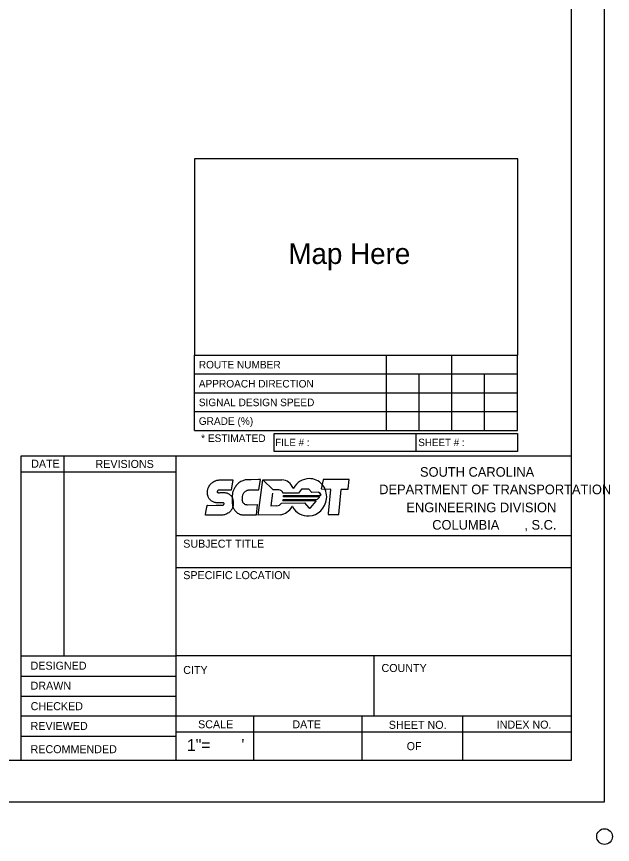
# Model space of a CAD drawing. Extents: x 0 to 3.01, y -0.05 to 1.83.
# Drawn here: x 2.332 to 3.009, y -0.048 to 0.892 of the extents above; entities that cross this region are included whole.
import ezdxf

# ---------------------------------------------------------------- set-up
doc = ezdxf.new("R2010")
doc.units = 0
doc.layers.add('RD_SHT_IplotShp', color=7, linetype='Continuous')
doc.layers.add('TR_TS_Border', color=7, linetype='Continuous')

msp = doc.modelspace()

# ---------------------------------------------------------------- linework, layer by layer
at = {"layer": 'RD_SHT_IplotShp'}
msp.add_lwpolyline([(0, 0), (3, 0), (3, 1.83333), (0, 1.83333)], close=True, dxfattribs=at)
at = {"layer": 'TR_TS_Border'}
for p, q in [((3, 0), (3, 1.83333)), ((2.96235, 0.04747), (2.96235, 1.7754)), ((2.5341, 0.5078), (2.9009, 0.5078)), ((2.5341, 0.42197), (2.5341, 0.5078)), ((2.75213, 0.42197), (2.75213, 0.5078)), ((2.82652, 0.42197), (2.82652, 0.5078)), ((2.9009, 0.42197), (2.9009, 0.5078)), ((2.5341, 0.48634), (2.9009, 0.48634)), ((2.78932, 0.42197), (2.78932, 0.48634)), ((2.86371, 0.42197), (2.86371, 0.48634)), ((2.5341, 0.46489), (2.9009, 0.46489)), ((2.5341, 0.44343), (2.9009, 0.44343)), ((2.5341, 0.42197), (2.9009, 0.42197)), ((2.78565, 0.41865), (2.78565, 0.39826)), ((2.33721, 0.3932), (2.96235, 0.3932)), ((2.33721, 0.04747), (2.33721, 0.3932)), ((2.38563, 0.3932), (2.38563, 0.16574)), ((2.5133, 0.04747), (2.5133, 0.3932)), ((2.33721, 0.37501), (2.5133, 0.37501)), ((2.60654, 0.32587), (2.61156, 0.36609)), ((2.62327, 0.35444), (2.61156, 0.36609)), ((2.61156, 0.36609), (2.6334, 0.366)), ((2.61156, 0.36609), (2.62327, 0.35444)), ((2.68015, 0.36591), (2.67795, 0.35553)), ((2.68033, 0.36627), (2.68015, 0.36591)), ((2.68094, 0.36636), (2.68042, 0.36636)), ((2.70894, 0.36645), (2.68094, 0.36636)), ((2.70859, 0.35563), (2.70991, 0.36645)), ((2.70965, 0.36645), (2.70894, 0.36645)), ((2.70991, 0.36645), (2.70965, 0.36645)), ((2.62275, 0.35089), (2.62063, 0.33643)), ((2.62979, 0.35444), (2.62327, 0.35444)), ((2.65215, 0.35071), (2.6349, 0.35062)), ((2.63534, 0.34798), (2.67698, 0.34826)), ((2.65568, 0.35535), (2.65215, 0.35071)), ((2.66378, 0.35544), (2.65568, 0.35535)), ((2.66739, 0.35171), (2.66378, 0.35544)), ((2.67531, 0.3518), (2.66739, 0.35171)), ((2.67566, 0.35171), (2.67769, 0.34926)), ((2.67566, 0.35171), (2.67769, 0.34926)), ((2.67769, 0.34926), (2.67566, 0.35171)), ((2.67698, 0.34826), (2.67707, 0.3478)), ((2.67725, 0.34771), (2.67769, 0.34871)), ((2.67795, 0.35553), (2.68816, 0.35544)), ((2.68861, 0.3549), (2.68596, 0.32779)), ((2.6982, 0.32651), (2.70076, 0.3549)), ((2.7012, 0.35535), (2.70833, 0.35535)), ((2.63305, 0.33952), (2.65902, 0.3397)), ((2.67196, 0.34216), (2.63446, 0.34198)), ((2.6349, 0.34371), (2.6739, 0.34389)), ((2.67584, 0.34662), (2.63534, 0.34644)), ((2.65902, 0.3397), (2.66413, 0.33415)), ((2.66589, 0.33415), (2.67214, 0.3418)), ((2.6739, 0.34389), (2.67601, 0.34635)), ((2.67707, 0.3478), (2.67725, 0.34771)), ((2.62063, 0.33643), (2.62741, 0.33661)), ((2.63129, 0.32606), (2.60654, 0.32587)), ((2.68596, 0.32779), (2.68596, 0.32697)), ((2.68632, 0.32651), (2.6982, 0.32651)), ((2.96235, 0.30222), (2.5133, 0.30222)), ((2.96235, 0.26583), (2.5133, 0.26583)), ((2.33721, 0.16574), (2.5133, 0.16574)), ((2.96235, 0.16574), (2.5133, 0.16574)), ((2.73782, 0.16574), (2.73782, 0.09751)), ((2.33721, 0.143), (2.5133, 0.143)), ((2.33721, 0.12025), (2.5133, 0.12025)), ((2.96235, 0.09751), (2.33721, 0.09751)), ((2.60135, 0.04747), (2.60135, 0.09751)), ((2.72462, 0.04747), (2.72462, 0.09751)), ((2.83908, 0.04747), (2.83908, 0.09751)), ((2.96235, 0.07931), (2.5133, 0.07931)), ((2.33721, 0.07476), (2.5133, 0.07476)), ((0.16861, 0.04747), (2.96235, 0.04747)), ((0.02381, 0), (3, 0))]:
    msp.add_line(p, q, dxfattribs=at)
for points in [[(2.5341, 0.5078), (2.90153, 0.5078), (2.90153, 0.73062), (2.5341, 0.73062)], [(2.62439, 0.41865), (2.9009, 0.41865), (2.9009, 0.39826), (2.62439, 0.39826)]]:
    msp.add_lwpolyline(points, close=True, dxfattribs=at)
for points in [[(2.55609, 0.34061), (2.55539, 0.34098), (2.55451, 0.34134), (2.55372, 0.34171), (2.55301, 0.34216), (2.55231, 0.3428), (2.55169, 0.34343), (2.55125, 0.3438), (2.55072, 0.34453), (2.55046, 0.34516), (2.55011, 0.34589), (2.54958, 0.34662), (2.5494, 0.34735), (2.54914, 0.34789), (2.54905, 0.34853), (2.54887, 0.34908), (2.54878, 0.34953), (2.54878, 0.35017), (2.54878, 0.35153), (2.54878, 0.35217), (2.54878, 0.35326), (2.54887, 0.35417), (2.54905, 0.3549), (2.54931, 0.35581), (2.54967, 0.35663), (2.55002, 0.35735), (2.55046, 0.35826), (2.55072, 0.3589), (2.55134, 0.3599), (2.55204, 0.36063), (2.55275, 0.36154), (2.55354, 0.36227), (2.55424, 0.36272), (2.55504, 0.36336), (2.55609, 0.364), (2.55662, 0.36427), (2.5575, 0.36463), (2.55812, 0.36491), (2.55873, 0.36518), (2.55961, 0.36545), (2.5605, 0.36563), (2.56129, 0.36573), (2.56208, 0.36582), (2.5627, 0.36582), (2.5634, 0.36582), (2.57247, 0.36591), (2.57775, 0.36591)], [(2.57775, 0.36591), (2.5759, 0.35426), (2.56199, 0.35426), (2.56155, 0.35417), (2.56102, 0.35408), (2.56076, 0.3539), (2.5605, 0.35372), (2.56023, 0.35353), (2.56014, 0.35335), (2.56005, 0.35317), (2.55997, 0.3529), (2.55988, 0.35262), (2.55988, 0.35244), (2.55988, 0.35208), (2.55997, 0.35208), (2.56014, 0.35171), (2.56023, 0.35162), (2.56041, 0.35153), (2.56076, 0.35144), (2.56094, 0.35144), (2.56138, 0.35135), (2.56243, 0.35135), (2.5634, 0.35144), (2.56411, 0.35144), (2.56499, 0.35153), (2.56763, 0.35153)], [(2.5774, 0.35171), (2.57731, 0.35089), (2.57714, 0.34999), (2.57705, 0.3488), (2.57696, 0.34798), (2.57696, 0.34707), (2.57696, 0.3468), (2.57687, 0.34644), (2.57687, 0.34616), (2.57678, 0.3458), (2.57678, 0.34534), (2.57678, 0.34498), (2.5767, 0.34462), (2.5767, 0.34398), (2.5767, 0.34353), (2.5767, 0.34307), (2.5767, 0.34262), (2.5767, 0.34234), (2.5767, 0.34189), (2.5767, 0.34134), (2.57678, 0.34052), (2.57687, 0.3397), (2.57696, 0.33898), (2.57705, 0.33834), (2.57714, 0.33752), (2.57731, 0.33697), (2.57731, 0.33643), (2.5774, 0.33588), (2.57766, 0.33515), (2.57784, 0.33452), (2.57793, 0.33406), (2.57846, 0.33324), (2.57899, 0.33243), (2.57934, 0.33179), (2.57978, 0.33115), (2.58031, 0.33061), (2.58101, 0.32988), (2.58163, 0.32933), (2.58224, 0.32879), (2.58295, 0.32824), (2.58392, 0.32779), (2.58471, 0.32724), (2.58532, 0.32697), (2.58603, 0.32669), (2.58665, 0.3266), (2.58709, 0.32642), (2.58797, 0.32624), (2.58841, 0.32624), (2.58911, 0.32606), (2.58964, 0.32606), (2.60417, 0.32606), (2.60426, 0.32624), (2.60434, 0.32624), (2.60575, 0.33743), (2.60531, 0.33743), (2.59448, 0.33734), (2.59351, 0.33743), (2.59272, 0.33752), (2.59202, 0.3377), (2.59131, 0.33807), (2.5907, 0.33852), (2.58999, 0.33916), (2.58946, 0.3398), (2.58911, 0.34034), (2.58885, 0.34098), (2.58858, 0.34161), (2.58841, 0.34216), (2.58832, 0.34307), (2.58841, 0.34416), (2.58849, 0.34516), (2.58858, 0.34644), (2.58867, 0.34716), (2.58885, 0.34835), (2.58911, 0.34898), (2.58946, 0.34971), (2.58982, 0.35053), (2.59026, 0.35126), (2.59096, 0.3518), (2.59158, 0.35253), (2.59219, 0.35308), (2.59325, 0.35362), (2.59404, 0.35408), (2.59466, 0.35426), (2.5951, 0.35435), (2.59589, 0.35453), (2.59677, 0.35453), (2.60716, 0.35453), (2.60734, 0.35463), (2.60892, 0.36645)], [(2.60892, 0.36645), (2.60672, 0.36645), (2.59853, 0.36609), (2.5958, 0.36609), (2.59413, 0.36609), (2.59298, 0.366), (2.59158, 0.36582), (2.5907, 0.36563), (2.5899, 0.36536), (2.58893, 0.36491), (2.58797, 0.36454), (2.58682, 0.364), (2.58568, 0.36327), (2.58453, 0.36245), (2.58409, 0.36209), (2.58339, 0.36154), (2.58251, 0.36081), (2.5818, 0.35999), (2.58101, 0.35899), (2.58048, 0.35808), (2.57987, 0.35726), (2.57951, 0.35663), (2.57907, 0.35581), (2.57872, 0.35499), (2.57819, 0.35408), (2.57793, 0.35326), (2.57766, 0.35244), (2.5774, 0.35171)], [(2.56763, 0.35153), (2.56842, 0.35144), (2.56921, 0.35135), (2.56992, 0.35117), (2.5708, 0.35099), (2.57141, 0.3508), (2.57203, 0.35053), (2.57247, 0.35035), (2.57317, 0.34989), (2.57397, 0.34944), (2.57449, 0.34898), (2.57502, 0.34871), (2.57538, 0.34826), (2.5759, 0.34762), (2.57617, 0.34726), (2.57661, 0.3468), (2.5767, 0.34662)], [(2.5767, 0.34662), (2.57687, 0.34616), (2.57696, 0.3458), (2.57714, 0.34544), (2.57714, 0.34516), (2.57731, 0.3448), (2.5774, 0.34425), (2.57749, 0.34398), (2.57749, 0.3438), (2.57758, 0.34353), (2.57766, 0.34325), (2.57766, 0.34307), (2.57766, 0.34289), (2.57775, 0.34271), (2.57775, 0.34234), (2.57784, 0.34198), (2.57784, 0.34171), (2.57793, 0.34152), (2.57793, 0.34116), (2.57793, 0.34098), (2.57802, 0.34061), (2.57802, 0.34034), (2.57802, 0.33989), (2.57802, 0.33961), (2.57802, 0.33961), (2.57802, 0.33925), (2.57802, 0.33889), (2.57802, 0.33852), (2.57802, 0.33834), (2.57802, 0.33825), (2.57802, 0.33798), (2.57802, 0.33761), (2.57802, 0.33734), (2.57793, 0.33707), (2.57793, 0.3367), (2.57793, 0.33643), (2.57784, 0.33625), (2.57784, 0.33588), (2.57775, 0.3357), (2.57766, 0.33543), (2.57758, 0.33515), (2.57758, 0.33488), (2.57749, 0.3347), (2.5774, 0.33443), (2.57731, 0.33397), (2.57714, 0.33361), (2.57687, 0.33288), (2.57661, 0.33252), (2.57617, 0.33206), (2.57599, 0.33179), (2.57564, 0.33133), (2.5752, 0.3307), (2.57458, 0.33006), (2.57379, 0.32924), (2.573, 0.3286), (2.57194, 0.32797), (2.5708, 0.32724), (2.56992, 0.32688), (2.56904, 0.32651), (2.56824, 0.32624), (2.56727, 0.32606), (2.56631, 0.32587), (2.56569, 0.32587), (2.55697, 0.32569), (2.54658, 0.32569), (2.54641, 0.32587), (2.54641, 0.32587), (2.54641, 0.32606), (2.54641, 0.32624), (2.54702, 0.32906), (2.54861, 0.3367), (2.54861, 0.33679), (2.54878, 0.33697), (2.54878, 0.33697), (2.54922, 0.33679), (2.55882, 0.33697), (2.56543, 0.33697), (2.56587, 0.33707), (2.56622, 0.33707), (2.56657, 0.33725), (2.56701, 0.33743), (2.56719, 0.3377), (2.56736, 0.33788), (2.56754, 0.33834), (2.56763, 0.33861), (2.56763, 0.33898), (2.56763, 0.33916), (2.56754, 0.33925), (2.56745, 0.33943), (2.56736, 0.33961), (2.56719, 0.3398), (2.56692, 0.33989), (2.56675, 0.33998), (2.56657, 0.33998), (2.55935, 0.33989), (2.559, 0.33989), (2.55873, 0.33998), (2.55821, 0.33998), (2.55777, 0.34016), (2.5568, 0.34034), (2.55609, 0.34061)]]:
    msp.add_lwpolyline(points, dxfattribs=at)
msp.add_circle((3, -0.03949), 0.00894, dxfattribs=at)
for centre, major_axis, start_param, end_param in [((2.6647, 0.34487), (0, 0.02245), 0.022191, 1.026566), ((2.66477, 0.34683), (0, 0.02049), 4.590524, 6.310821), ((2.63262, 0.35074), (0, 0.01526), 5.101309, 6.228759), ((2.68039, 0.3662), (0, 0.000124), 0, 1.322539), ((2.63014, 0.34926), (0, 0.0052), 4.972804, 6.356492), ((2.64626, 0.35662), (0, 0.000247), 1.959716, 4.168159), ((2.67532, 0.35135), (0, 0.000494), 5.415198, 6.296193), ((2.6773, 0.34891), (0, -0.000494), 1.075193, 2.27985), ((2.68818, 0.35493), (0, -0.000494), 1.467405, 3.132152), ((2.70121, 0.35484), (0, 0.000494), 0, 1.477178), ((2.70828, 0.35571), (0, -0.000371), 0, 1.445107), ((2.62747, 0.3439), (0, -0.00733), 6.271457, 7.213216), ((2.62309, 0.34711), (0, -0.01293), 1.163643, 1.303168), ((2.62318, 0.34708), (0, 0.01283), 4.666228, 4.78426), ((2.66333, 0.34697), (0, -0.02202), 0.045208, 1.450715), ((2.67198, 0.34195), (0, 0.000247), 3.995698, 6.287734), ((2.67586, 0.34648), (0, 0.000185), 3.986308, 6.285649), ((2.62825, 0.34699), (0, -0.02112), 0.151273, 0.993651), ((2.64527, 0.33534), (0, -0.000247), 2.058368, 4.135244), ((2.6622, 0.34479), (0, -0.01993), 5.19996, 6.392752), ((2.66499, 0.33501), (0, -0.00124), 5.487728, 7.137097), ((2.68632, 0.32692), (0, -0.000371), 4.712389, 6.283185)]:
    msp.add_ellipse(centre, major_axis=major_axis, ratio=0.950042, start_param=start_param, end_param=end_param, dxfattribs=at)

# ---------------------------------------------------------------- texts
for s, height, p in [('Map Here', 0.023595, (2.64071, 0.61124)), ('ROUTE NUMBER', 0.008578, (2.53894, 0.49253)), ('APPROACH DIRECTION', 0.008578, (2.53894, 0.47089)), ('SIGNAL DESIGN SPEED', 0.008578, (2.53894, 0.44966)), ('GRADE (%)', 0.008578, (2.53894, 0.42842)), ('* ESTIMATED', 0.008578, (2.5416, 0.40897)), ('FILE # :', 0.008333, (2.62576, 0.40429)), ('SHEET # :', 0.008333, (2.78836, 0.40429)), ('DATE', 0.009098, (2.34851, 0.37974)), ('REVISIONS', 0.009098, (2.42158, 0.37946)), ('SOUTH CAROLINA', 0.010918, (2.79026, 0.36946)), ('DEPARTMENT OF TRANSPORTATION', 0.010918, (2.74392, 0.34962)), ('ENGINEERING DIVISION', 0.010918, (2.77479, 0.32915)), ('       COLUMBIA       , S.C.', 0.010918, (2.77577, 0.30932)), ('SUBJECT TITLE', 0.0090979, (2.52126, 0.28884)), ('SPECIFIC LOCATION', 0.0090979, (2.52126, 0.25309)), ('DESIGNED', 0.009098, (2.34783, 0.15019)), ('CITY', 0.009098, (2.52126, 0.14529)), ('COUNTY', 0.009098, (2.74654, 0.14756)), ('DRAWN', 0.009098, (2.34783, 0.12744)), ('CHECKED', 0.009098, (2.34783, 0.10415)), ('REVIEWED', 0.009098, (2.34783, 0.08168)), ('SCALE', 0.009098, (2.53813, 0.08359)), ('DATE', 0.009098, (2.64524, 0.0835)), ('SHEET NO.', 0.009098, (2.75485, 0.08295)), ('INDEX NO.', 0.009098, (2.87747, 0.08322)), ('1"=       \'', 0.013434, (2.52548, 0.05786)), ('OF', 0.009098, (2.77516, 0.05875)), ('RECOMMENDED', 0.0090985, (2.34783, 0.05529))]:
    msp.add_text(s, height=height, dxfattribs=at).set_placement(p)

doc.saveas('drawing.dxf')
